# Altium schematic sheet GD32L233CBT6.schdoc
size 127 x 101 mm
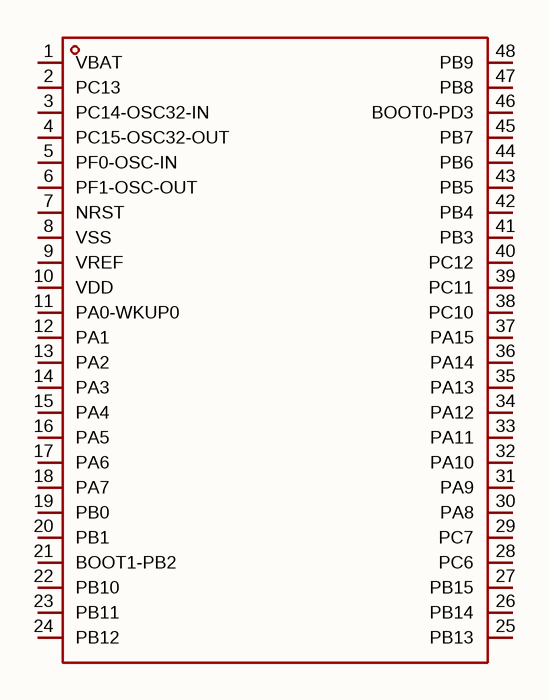
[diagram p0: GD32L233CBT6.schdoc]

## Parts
U?  gd32l233cbt6  [LQFP-48_L7.0-W7.0-P0.50-LS9.0-BL]  (value not drawn)

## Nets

Not connected (* = marked no-connect by the designer): U? 1(VBAT) 2(PC13) 3(PC14-OSC32-IN) 4(PC15-OSC32-OUT) 5(PF0-OSC-IN) 6(PF1-OSC-OUT) 7(NRST) 8(VSS) 9(VREF) 10(VDD) 11(PA0-WKUP0) 12(PA1) 13(PA2) 14(PA3) 15(PA4) 16(PA5) 17(PA6) 18(PA7) 19(PB0) 20(PB1) 21(BOOT1-PB2) 22(PB10) 23(PB11) 24(PB12) 25(PB13) 26(PB14) 27(PB15) 28(PC6) 29(PC7) 30(PA8) 31(PA9) 32(PA10) 33(PA11) 34(PA12) 35(PA13) 36(PA14) 37(PA15) 38(PC10) 39(PC11) 40(PC12) 41(PB3) 42(PB4) 43(PB5) 44(PB6) 45(PB7) 46(BOOT0-PD3) 47(PB8) 48(PB9)

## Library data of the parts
U? = gd32l233cbt6: CPU内核:ARM Cortex-M23;CPU最大主频:64MHz;CPU位数:32 Bit;; Manufacturer: GigaDevice(兆易创新); AddInBom: yes; ModelId: 093be70396ff421eb2cdb946d5311efc; ModelName: LQFP-48_L7.0-W7.0-H1.4-LS9.0-P0.50; ModelTransform: 354.331,354.331,0,0,0,0,0,0,0; CPU Maximum Speed: 64MHz; Core Size: 32 Bit; Program Storage Size: 128KB; Program Memory Type: FLASH; Number of I/O: 59; ADC (Bit): 12bit; Voltage - Supply: 1.71V~3.63V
